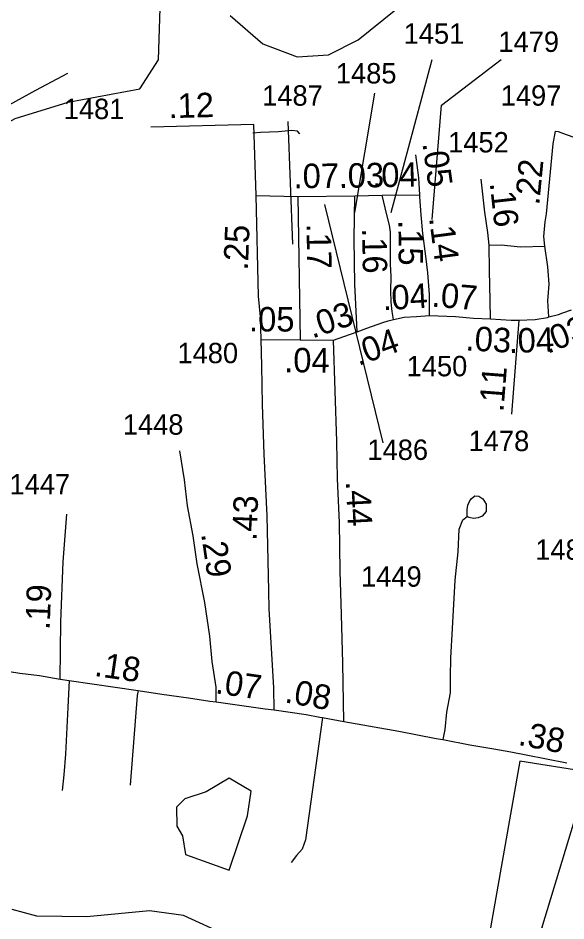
# Model space of a CAD drawing. Extents: x 2290615 to 2522933, y 819489 to 1012715.
# Drawn here: x 2385868 to 2389226, y 981982 to 987517 of the extents above; entities that cross this region are included whole.
import ezdxf

# ---------------------------------------------------------------- set-up
doc = ezdxf.new("R2010")
doc.units = 0
for name, color, linetype in [('Exist Boundary Political City Limit New', 7, 'Continuous'), ('Exist Boundary Political City Limit Old', 7, 'Continuous'), ('Exist Hydrographic Creek Single Shore', 7, 'Continuous'), ('Exist Hydrographic Misc Water Feature', 7, 'Continuous'), ('Exist Hydrographic Pond Under 1500 Sq Ft', 7, 'Continuous'), ('Exist Road Non-System Type 51', 7, 'Continuous'), ('Exist Road Primary US Attributed', 7, 'Continuous'), ('Exist Road Primary US Mileage Hundredths English Label', 7, 'Continuous'), ('Exist Road Secondary Mileage Hundredths English Label', 7, 'Continuous'), ('Exist Road Secondary Mileage Tenths English Label', 7, 'Continuous'), ('Exist Road Secondary Type 20 Attributed', 7, 'Continuous'), ('Exist Road Secondary Type 51 Attributed', 7, 'Continuous'), ('Exist Road Secondary Type 51 Number Label', 7, 'Continuous'), ('Map Preparation Boundary City Limit Buffer Line', 7, 'Continuous')]:
    doc.layers.add(name, color=color, linetype=linetype)

msp = doc.modelspace()

# ---------------------------------------------------------------- linework, layer by layer
at = {"layer": 'Exist Boundary Political City Limit New'}
msp.add_lwpolyline([(2390853.6, 986356.8), (2389493.5, 981816), (2389078.7, 981936.4), (2389369.2, 982893.4), (2388943.6, 982960.5), (2388694.8, 981544.7), (2388565.3, 980833.1), (2388622.3, 980658.4), (2388645.5, 980577.3), (2388704.6, 980503.6), (2388847.4, 980382.6), (2388912.3, 980324.6), (2389037.7, 980322.3), (2389279, 980347.8), (2389265.1, 980612.1), (2389279, 980723.4), (2389336.9, 980814.4), (2393618.8, 980687.8), (2394515, 980647.9)], dxfattribs=at)
at = {"layer": 'Exist Boundary Political City Limit Old'}
msp.add_lwpolyline([(2390853.6, 986356.8), (2389493.5, 981816), (2389078.7, 981936.4), (2389369.2, 982893.4), (2388943.6, 982960.5), (2388694.8, 981544.7), (2388565.3, 980833.1), (2388622.3, 980658.4), (2388645.5, 980577.3), (2388704.6, 980503.6), (2388847.4, 980382.6), (2388912.3, 980324.6), (2389037.7, 980322.3), (2389279, 980347.8), (2389265.1, 980612.1), (2389279, 980723.4), (2389316.4, 980858.1), (2393618.8, 980687.8), (2394515, 980647.9)], dxfattribs=at)
at = {"layer": 'Exist Hydrographic Creek Single Shore'}
for points in [[(2387167.6, 987532.4), (2387369.5, 987360.1), (2387578.5, 987280.2), (2387770.4, 987291.3), (2387952.5, 987384.1), (2388488.5, 987816.6)], [(2387150.5, 981891.7), (2386881.5, 982015.2), (2386673.6, 982042.7), (2386290.5, 982007.2), (2385982.6, 982011), (2385831.6, 982050.7)]]:
    msp.add_lwpolyline(points, dxfattribs=at)
at = {"layer": 'Exist Hydrographic Misc Water Feature'}
msp.add_lwpolyline([(2384151.1, 984921), (2384765.6, 985142.1), (2385095.5, 985438), (2385266.5, 985701.2), (2385378.5, 986050.5), (2385456.4, 986493.5), (2385504.6, 986587.5), (2385693.4, 986815.2), (2385850.5, 986900.5), (2386174.5, 987002.4), (2386614.5, 987082.9), (2386728.5, 987261.6), (2386740.4, 987642.9), (2386781.4, 987729.9), (2386871.5, 987812.4)], dxfattribs=at)
at = {"layer": 'Exist Hydrographic Pond Under 1500 Sq Ft'}
msp.add_lwpolyline([(2387161.6, 982292.6), (2387273.6, 982625.6), (2387296.5, 982777.5), (2387162.6, 982857.3), (2387021.6, 982772.7), (2386889.5, 982731.2), (2386839.7, 982679.9), (2386841.5, 982561.8), (2386875.6, 982504.1), (2386893.6, 982389.9), (2387161.6, 982292.6)], dxfattribs=at)
at = {"layer": 'Exist Road Non-System Type 51'}
msp.add_line((2387327, 986428.9), (2387580.5, 986423.8), dxfattribs=at)
for points in [[(2384469.8, 986732), (2384629.6, 986754.2), (2384959, 986792.5), (2385134.9, 986802.8), (2385296.7, 986815), (2385434.5, 986826.7), (2385496.2, 986837.6), (2385544.2, 986850.2), (2385689.2, 986918.2), (2385977.1, 987076), (2386173.6, 987178.5)], [(2384469.8, 986732), (2384629.6, 986754.2), (2384959, 986792.5), (2385134.9, 986802.8), (2385296.7, 986815), (2385434.5, 986826.7), (2385496.2, 986837.6), (2385544.2, 986850.2), (2385689.2, 986918.2), (2385977.1, 987076), (2386173.6, 987178.5)], [(2387594.6, 986808.4), (2387593.9, 986808.7), (2387580.5, 986823.8), (2387546.9, 986828.8), (2387464.6, 986820.4), (2387353.7, 986815.4), (2387308.1, 986812)], [(2389162.8, 986824.6), (2389177.9, 986821.1), (2389227, 986804.3), (2389246.4, 986798.1), (2389262.9, 986790.1), (2389292.6, 986779.7), (2389324.3, 986763.8), (2389369.6, 986733.8)], [(2388755.2, 986124.3), (2388829.2, 986126), (2388948.9, 986115.5), (2389096.7, 986119)], [(2388621.4, 984461.4), (2388620.9, 984503.4), (2388624.6, 984531.3), (2388636.2, 984553.6), (2388646, 984569.6), (2388667.7, 984587.9), (2388691.7, 984586.3), (2388717.9, 984568.6), (2388738.4, 984536.8), (2388737.1, 984490.9), (2388713.4, 984462.5), (2388689.4, 984452.3), (2388659.5, 984449.9), (2388633.5, 984455.4), (2388621.4, 984461.4)], [(2388621.4, 984461.4), (2388620.9, 984503.4), (2388624.6, 984531.3), (2388636.2, 984553.6), (2388646, 984569.6), (2388667.7, 984587.9), (2388691.7, 984586.3), (2388717.9, 984568.6), (2388738.4, 984536.8), (2388737.1, 984490.9), (2388713.4, 984462.5), (2388689.4, 984452.3), (2388659.5, 984449.9), (2388633.5, 984455.4), (2388621.4, 984461.4)], [(2388472.7, 983094), (2388474.4, 983093.7), (2388485.7, 983156), (2388497.1, 983261.8), (2388519.7, 983381), (2388519.7, 983475.5), (2388521.6, 983594.7), (2388531.1, 983774.3), (2388548, 984070), (2388566.9, 984244), (2388572.6, 984383.9), (2388595.3, 984440.7), (2388621.4, 984461.4)], [(2386181.2, 983455.9), (2386173, 983290.3), (2386159.5, 983004.6), (2386147.8, 982876.8), (2386137.7, 982781)], [(2386604.6, 983394.4), (2386597.9, 983364.2), (2386555.9, 982813)], [(2387733.7, 983228.5), (2387629.3, 982479.1), (2387609.1, 982422), (2387575.5, 982383.3), (2387542.1, 982340)]]:
    msp.add_lwpolyline(points, dxfattribs=at)
at = {"layer": 'Exist Road Primary US Attributed'}
for points in [[(2385416.6, 983569.2), (2385506.8, 983556.1), (2385621.4, 983539), (2385763.7, 983519.8), (2385879, 983501.2), (2386000.3, 983485.6), (2386127.3, 983464.8)], [(2386127.3, 983464.8), (2386181.2, 983455.9), (2386604.6, 983394.4), (2386749.1, 983372.9), (2386912, 983349.4), (2387042.7, 983329.2), (2387083, 983325.9)], [(2387083, 983325.9), (2387269.4, 983299), (2387381.9, 983282.2), (2387437.4, 983275.4)], [(2387437.4, 983275.4), (2387634.7, 983246.9), (2387718.6, 983231.8), (2387733.7, 983228.5), (2387864.7, 983204.9)], [(2387864.7, 983204.9), (2388202.3, 983144.4), (2388430.7, 983100.7), (2388472.7, 983094), (2388638.2, 983062.3), (2388784.3, 983037.1), (2388888.4, 983018.6), (2388982.5, 983000.1), (2389232, 982951.5)]]:
    msp.add_lwpolyline(points, dxfattribs=at)
at = {"layer": 'Exist Road Secondary Type 20 Attributed'}
msp.add_lwpolyline([(2389120.9, 985685.4), (2389115.2, 985783.4), (2389124, 985885.5), (2389115.2, 985991.3), (2389096.7, 986119), (2389091.5, 986178.9), (2389098.5, 986268.7), (2389108.2, 986317.2), (2389148.9, 986746.7), (2389162.8, 986824.6)], dxfattribs=at)
at = {"layer": 'Exist Road Secondary Type 51 Attributed'}
for p, q in [((2387933.1, 986427.2), (2388099.4, 986430.5)), ((2388099.4, 986430.5), (2388330, 986433.8)), ((2388937.4, 985665.3), (2388892.5, 985088.3)), ((2387357.7, 985545.7), (2387597.5, 985545)), ((2387597.5, 985545), (2387802.4, 985543.1))]:
    msp.add_line(p, q, dxfattribs=at)
for points in [[(2387312.6, 986865.5), (2386682.7, 986849)], [(2387357.7, 985545.7), (2387354.3, 985685.4), (2387342.6, 985813.1), (2387327, 986428.9), (2387312.6, 986865.5)], [(2388330, 986433.8), (2388325.7, 986538.1), (2388305.6, 986679.3)], [(2388764, 985672.2), (2388762.3, 985786), (2388758.7, 985969.2), (2388755.2, 986124.3), (2388748.2, 986203.5), (2388728.8, 986326.9), (2388705.9, 986529.5)], [(2387583.8, 986423.8), (2387933.1, 986427.2)], [(2387583.8, 986423.8), (2387597.5, 985545)], [(2387946.6, 985593.3), (2387944.9, 985636.8), (2387933.2, 985885.1), (2387928.1, 986161.8), (2387933.1, 986427.2)], [(2388169.4, 985668.8), (2388161.1, 985718.2), (2388154.7, 985774.5), (2388153, 985845.1), (2388154.7, 985932.5), (2388151.3, 986009.1), (2388150.2, 986205.1), (2388144.6, 986247.7), (2388129.5, 986309.9), (2388099.4, 986430.5)], [(2388389.9, 985693.5), (2388389.6, 985821.5), (2388379.5, 985954.3), (2388367.8, 986056.8), (2388349.3, 986196.3), (2388339.2, 986310.6), (2388330.7, 986422.2), (2388330, 986433.8)], [(2389120.9, 985685.4), (2389181.2, 985699.7), (2389207.6, 985710.2), (2389260.5, 985727.9)], [(2387946.6, 985593.3), (2388006.5, 985615), (2388103.9, 985650.3), (2388137.5, 985660.4), (2388169.4, 985668.8)], [(2388169.4, 985668.8), (2388235.4, 985683), (2388310.9, 985687.6), (2388389.9, 985693.5)], [(2388389.9, 985693.5), (2388549.3, 985686.5), (2388660.1, 985677.3), (2388764, 985672.2)], [(2388764, 985672.2), (2388891.6, 985665.3), (2388937.4, 985665.3)], [(2388937.4, 985665.3), (2389038.6, 985668.6), (2389112.5, 985680.4), (2389120.9, 985685.4)], [(2387802.4, 985543.1), (2387865.5, 985564.6), (2387946.6, 985593.3)], [(2387437.4, 983275.4), (2387436.3, 983410.6), (2387407.7, 983894.7), (2387404.4, 984005.6), (2387396, 984464.4), (2387375.9, 984844.2), (2387367.5, 985147.5), (2387362.4, 985385.5), (2387357.7, 985545.7)], [(2387864.7, 983204.9), (2387859.4, 983561.8), (2387851.1, 983860.3), (2387842.7, 984126.7), (2387839.3, 984424.2), (2387825.9, 984691.8), (2387822.6, 984922.1), (2387802.4, 985543.1)], [(2387083, 983325.9), (2387082.3, 983415.4), (2387058.8, 983571.7), (2387043.7, 983728), (2387013.5, 983933.1), (2386966.5, 984170.8), (2386941.3, 984342.2), (2386907.8, 984526.4), (2386887.6, 984686), (2386859.1, 984864.2)], [(2386127.3, 983464.8), (2386130.1, 983815.8), (2386143.9, 984184.2), (2386166.7, 984474.8)]]:
    msp.add_lwpolyline(points, dxfattribs=at)
at = {"layer": 'Exist Road Secondary Type 51 Number Label'}
for p, q in [((2388155.2, 986324.8), (2388406, 987263.7)), ((2387933, 986324.8), (2388054.8, 987055.9)), ((2387553.1, 986131.3), (2387524.4, 986883.9)), ((2387746.6, 986375), (2388105, 984912.8))]:
    msp.add_line(p, q, dxfattribs=at)
msp.add_lwpolyline([(2388406, 986281.8), (2388463.4, 986984.2), (2388828.9, 987263.7)], dxfattribs=at)
at = {"layer": 'Map Preparation Boundary City Limit Buffer Line'}
msp.add_lwpolyline([(2390853.6, 986356.8), (2389493.5, 981816), (2389078.7, 981936.4), (2389369.2, 982893.4), (2388943.6, 982960.5), (2388694.8, 981544.7), (2388565.3, 980833.1), (2388622.3, 980658.4), (2388645.5, 980577.3), (2388704.6, 980503.6), (2388847.4, 980382.6), (2388912.3, 980324.6), (2389037.7, 980322.3), (2389279, 980347.8), (2389265.1, 980612.1), (2389279, 980723.4), (2389336.9, 980814.4), (2393618.8, 980687.8), (2394515, 980647.9)], dxfattribs=at)

# ---------------------------------------------------------------- texts
at = {"layer": 'Exist Road Primary US Mileage Hundredths English Label'}
for s, rotation, p in [('.18', 351.7316, (2386331.2, 983484.6)), ('.07', 351.792, (2387072.8, 983377.9)), ('.08', 349.7893, (2387497.9, 983322.4)), ('.38', 348.9906, (2388928.6, 983061.5))]:
    msp.add_text(s, height=150, rotation=rotation, dxfattribs=at).set_placement(p)
at = {"layer": 'Exist Road Secondary Mileage Hundredths English Label'}
for s, rotation, p in [('.12', 1.5035, (2386792.1, 986903.2)), ('.05', 278.1248, (2388346.1, 986748.8)), ('.22', 84.5816, (2389062.7, 986367)), ('.07', 0.546, (2387557.5, 986473.6)), ('.03', 1.1581, (2387834.7, 986475.2)), ('.04', 0.8131, (2388039.8, 986479.7)), ('.16', 276.4446, (2388758.9, 986505.7)), ('.15', 270.3331, (2388199.7, 986278.3)), ('.14', 277.5444, (2388387.1, 986291.8)), ('.17', 270.8902, (2387636.4, 986256.9)), ('.16', 271.0391, (2387976.9, 986228.2)), ('.04', 3.4711, (2388105.5, 985725.2)), ('.07', 355.2814, (2388399.7, 985749)), ('.03', 18.8437, (2387672.1, 985551.5)), ('.05', 359.8447, (2387283.8, 985595.9)), ('.03', 21.8174, (2389113.3, 985457.1)), ('.04', 19.9165, (2387954.3, 985383.4)), ('.03', 356.9302, (2388608.4, 985480.2)), ('.04', 1.8742, (2388877, 985463.2)), ('.04', 359.461, (2387498.9, 985345.9)), ('.11', 85.5513, (2388843.2, 985099.2)), ('.44', 272.8623, (2387876.8, 984675.7)), ('.29', 278.3604, (2386990, 984354.7))]:
    msp.add_text(s, height=150, rotation=rotation, dxfattribs=at).set_placement(p)
at = {"layer": 'Exist Road Secondary Mileage Tenths English Label'}
for s, p in [('.25', (2387277, 985968.7)), ('.43', (2387329.7, 984310.1)), ('.19', (2386061.7, 983764))]:
    msp.add_text(s, height=150, rotation=87.8674, dxfattribs=at).set_placement(p)
at = {"layer": 'Exist Road Secondary Type 51 Number Label'}
for s, p in [('1451', (2388231.8, 987359.9)), ('1479', (2388812.4, 987309.7)), ('1485', (2387816.1, 987116.2)), ('1487', (2387364.5, 986980)), ('1497', (2388826.7, 986980)), ('1481', (2386148.1, 986898)), ('1452', (2388504.2, 986693.3)), ('1480', (2386845.2, 985401.1)), ('1450', (2388249.9, 985320.9)), ('1448', (2386510.2, 984962.9)), ('1478', (2388629.8, 984862.2)), ('1486', (2388009.6, 984808.2)), ('1447', (2385815.9, 984596.7)), ('1489', (2389038.4, 984195.6)), ('1449', (2387970.4, 984030.8))]:
    msp.add_text(s, height=125, dxfattribs=at).set_placement(p)

doc.saveas('drawing.dxf')
